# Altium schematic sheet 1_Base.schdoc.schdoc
size 309 x 223 mm; Symbol: Sheet-Symbol_A4; Device: Sheet-Symbol_A4; Company: Velizy Astro Club; Drawed: Paul V.; Reviewed: Denis G.; Version: V1.0; Page Size: A4; @Project Name: AstrOnStep; @Page Count: 2; @Update Date: 2024-04-21; @Create Date: 2024-03-13; @Schematic Name: AstrOnStep SCH; Part Number: AstrOnStep-v1.0; @Page No: 1; @Page Name: Base
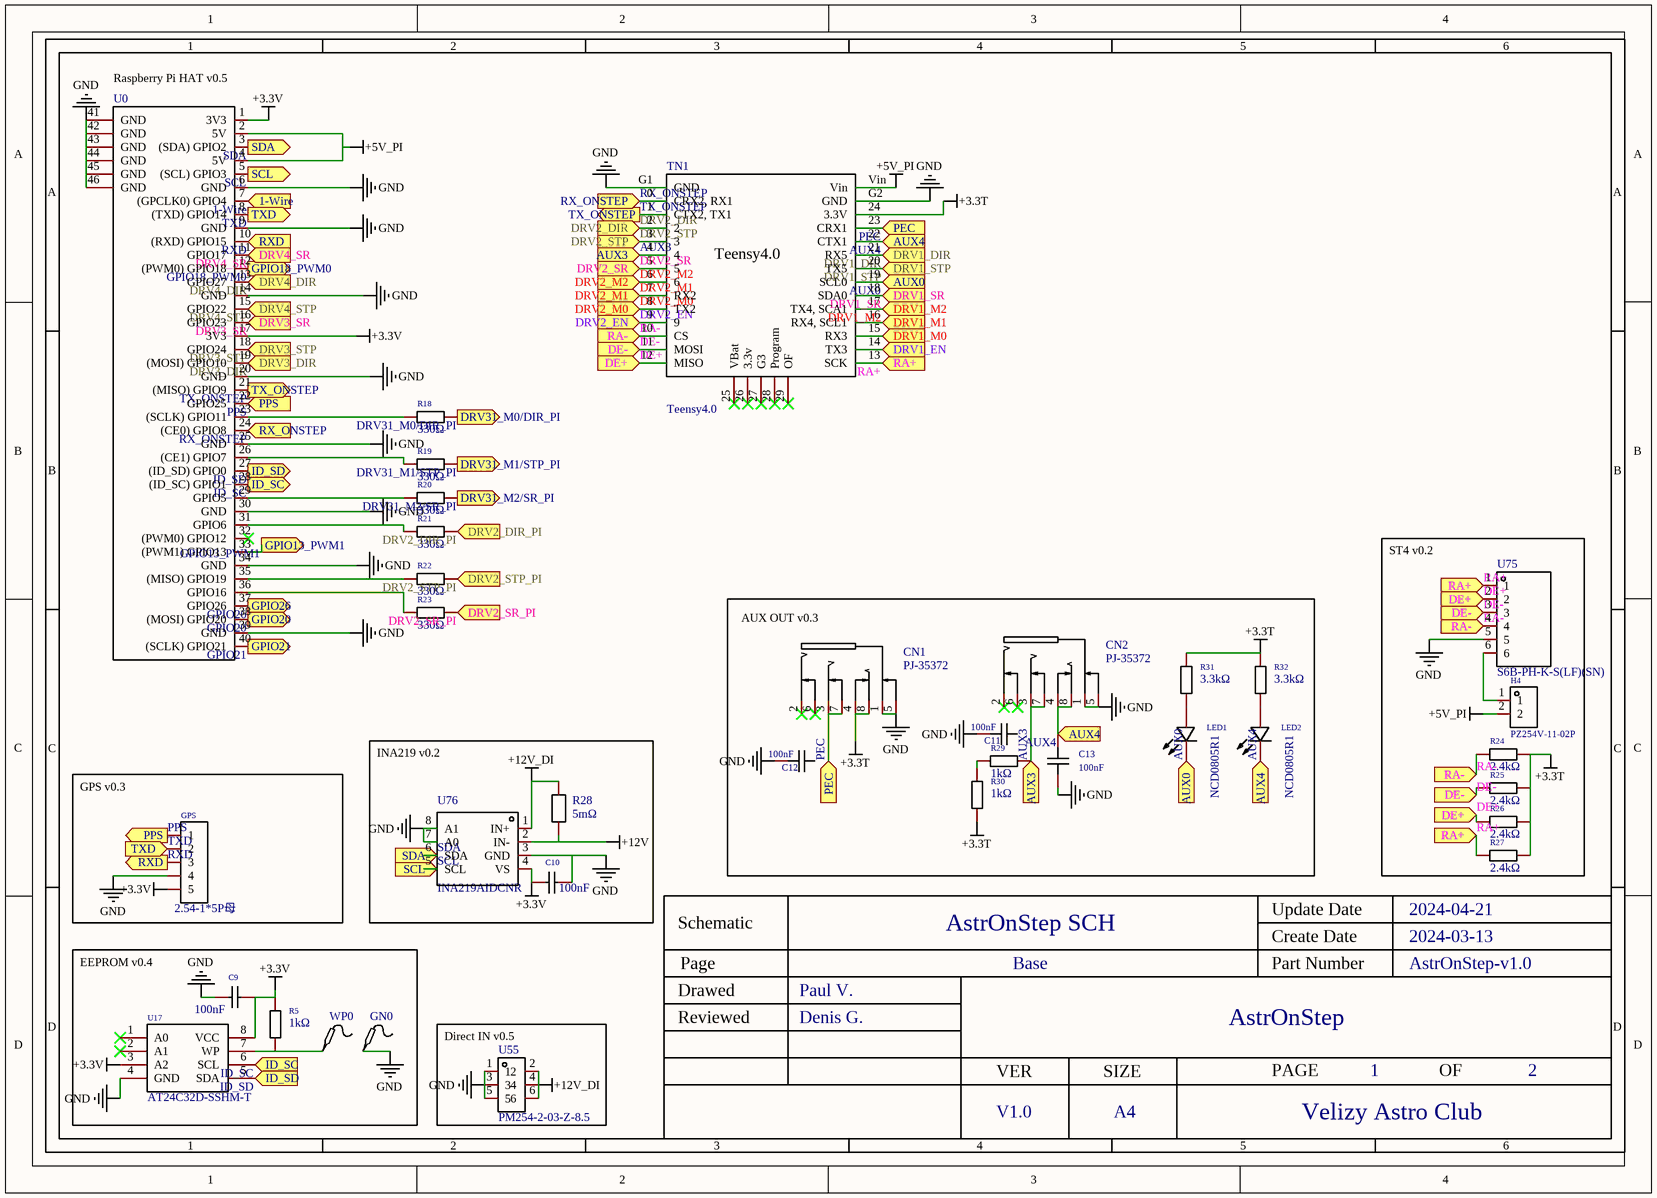
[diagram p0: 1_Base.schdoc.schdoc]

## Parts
C9  100nF  [C0402]
C10  100nF  [C0402]
C11  100nF  [C0603]
C12  100nF  [C0603]
C13  100nF  [C0603]
CN1  PJ-35372  [AUDIO-TH_PJ-35372]
CN2  PJ-35372  [AUDIO-TH_PJ-35372]
GN0  Test-Point  [Test-Point-0.5mm]  (value not drawn)
GPS  2.54-1*5P母  [HDR-TH_5P-P2.54-V-F]
H4  PZ254V-11-02P  [HDR-TH_2P-P2.54-V-M]
LED1  NCD0805R1  [LED0805-R-RD]
LED2  NCD0805R1  [LED0805-R-RD]
R5  1kΩ  [R0402]
R18  330Ω  [R0402]
R19  330Ω  [R0402]
R20  330Ω  [R0402]
R21  330Ω  [R0402]
R22  330Ω  [R0402]
R23  330Ω  [R0402]
R24  2.4kΩ  [R0603]
R25  2.4kΩ  [R0603]
R26  2.4kΩ  [R0603]
R27  2.4kΩ  [R0603]
R28  5mΩ  [R2512]
R29  1kΩ  [R0402]
R30  1kΩ  [R0402]
R31  3.3kΩ  [R0402]
R32  3.3kΩ  [R0402]
TN1  Teensy4.0  [TEENSY4.0]
U0  RASPI HAT FULL  [RASBERRYPI-3-HAT-EXT]  (value not drawn)
U17  AT24C32D-SSHM-T  [SOIC-8_L5.0-W4.0-P1.27-LS6.0-BL]
U55  PM254-2-03-Z-8.5  [HDR-TH_6P-P2.54-V-F-R2-C3-S2.54]
U75  S6B-PH-K-S(LF)(SN)  [CONN-TH_6P-P2.00_S6B-PH-K-S-LF-SN]
U76  INA219AIDCNR  [SOT-23-8_L3.0-W1.7-P0.65-LS2.8-BR]
WP0  Test-Point  [Test-Point-0.5mm]  (value not drawn)

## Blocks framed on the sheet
ST4 v0.2: H4 R24-R27 U75
AUX OUT v0.3: C11-C13 CN1 CN2 LED1 LED2 R29-R32
GPS v0.3: GPS
INA219 v0.2: C10 R28 U76
EEPROM v0.4: C9 GN0 R5 U17 WP0
Direct IN v0.5: U55

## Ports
1-Wire (in), AUX0 (in), AUX3 (in), AUX4 (in), DE+ (in), DE- (in), DRV1_DIR (in), DRV1_EN (in), DRV1_M0 (in), DRV1_M1 (in), DRV1_M2 (in), DRV1_SR (in), DRV1_STP (in), DRV2_DIR (in), DRV2_DIR_PI (in), DRV2_EN (in), DRV2_M0 (in), DRV2_M1 (in), DRV2_M2 (in), DRV2_SR (in), DRV2_SR_PI (in), DRV2_STP (in), DRV2_STP_PI (in), DRV3_DIR (in), DRV3_SR (in), DRV3_STP (in), DRV4_DIR (in), DRV4_SR (in), DRV4_STP (in), DRV31_M0/DIR_PI (out), DRV31_M1/STP_PI (out), DRV31_M2/SR_PI (out), GPIO13_PWM1 (out), GPIO18_PWM0 (out), GPIO20 (out), GPIO21 (out), GPIO26 (out), ID_SC (in), ID_SC (out), ID_SD (in), ID_SD (out), PEC (in), PPS (in), PPS (out), RA+ (in), RA- (in), RX_ONSTEP (in), RXD (in), RXD (out), SCL (in), SCL (out), SDA (in), SDA (out), TX_ONSTEP (out), TXD (in), TXD (out)

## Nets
+3.3T: CN1.4 CN1.8 R24.1 R25.1 R26.1 R27.1 R30.1 R31.2 R32.2 TN1.24(3.3V)
+3.3V: C9.2 C10.1 GPS.5 R5.2 U0.1(3V3) U0.17(3V3) U17.3(A2) U17.8(VCC) U76.4(VS)
+5V_PI: H4.2 TN1.Vin U0.2(5V) U0.4(5V)
+12V: R28.1 U76.2(IN-)
+12V_DI: R28.2 U55.2 U55.4 U55.6 U76.1(IN+)
GND: C9.1 C10.2 C11.2 C12.2 C13.1 CN1.1 CN1.5 CN2.1 CN2.5 GN0.1 GPS.4 TN1.G1(GND) TN1.G2(GND) U0.6(GND) U0.9(GND) U0.14(GND) U0.20(GND) U0.25(GND) U0.30(GND) U0.34(GND) U0.39(GND) U0.41(GND) U0.42(GND) U0.43(GND) U0.44(GND) U0.45(GND) U0.46(GND) U17.4(GND) U55.1 U55.3 U55.5 U75.5 U76.3(GND) U76.7(A0) U76.8(A1)
1-Wire: U0.7((GPCLK0)_GPIO4) ; port 1-Wire
AUX0: LED1.2(-) TN1.19(SCL0) ; port AUX0
AUX3: CN2.3 CN2.7 R29.1 TN1.4 ; port AUX3
AUX4: C13.2 CN2.4 CN2.8 LED2.2(-) TN1.22(CTX1) ; port AUX4
DE+: R26.2 TN1.12(MISO) U75.2 ; port DE+
DE-: R25.2 TN1.11(MOSI) U75.3 ; port DE-
DRV1_DIR: TN1.21(RX5) ; port DRV1_DIR
DRV1_EN: TN1.14(TX3) ; port DRV1_EN
DRV1_M0: TN1.15(RX3) ; port DRV1_M0
DRV1_M1: TN1.16(RX4,_SCL1) ; port DRV1_M1
DRV1_M2: TN1.17(TX4,_SCA1) ; port DRV1_M2
DRV1_SR: TN1.18(SDA0) ; port DRV1_SR
DRV1_STP: TN1.20(TX5) ; port DRV1_STP
DRV2_DIR: TN1.2 ; port DRV2_DIR
DRV2_DIR_PI: R21.2 ; port DRV2_DIR_PI
DRV2_EN: TN1.9 ; port DRV2_EN
DRV2_M0: TN1.8(TX2) ; port DRV2_M0
DRV2_M1: TN1.7(RX2) ; port DRV2_M1
DRV2_M2: TN1.6 ; port DRV2_M2
DRV2_SR: TN1.5 ; port DRV2_SR
DRV2_SR_PI: R23.2 ; port DRV2_SR_PI
DRV2_STP: TN1.3 ; port DRV2_STP
DRV2_STP_PI: R22.2 ; port DRV2_STP_PI
DRV3_DIR: U0.19((MOSI)_GPIO10) ; port DRV3_DIR
DRV3_SR: U0.16(GPIO23) ; port DRV3_SR
DRV3_STP: U0.18(GPIO24) ; port DRV3_STP
DRV4_DIR: U0.13(GPIO27) ; port DRV4_DIR
DRV4_SR: U0.11(GPIO17) ; port DRV4_SR
DRV4_STP: U0.15(GPIO22) ; port DRV4_STP
DRV31_M0/DIR_PI: R18.2 ; port DRV31_M0/DIR_PI
DRV31_M1/STP_PI: R19.2 ; port DRV31_M1/STP_PI
DRV31_M2/SR_PI: R20.2 ; port DRV31_M2/SR_PI
GPIO13_PWM1: U0.33((PWM1)_GPIO13) ; port GPIO13_PWM1
GPIO18_PWM0: U0.12((PWM0)_GPIO18) ; port GPIO18_PWM0
GPIO20: U0.38((MOSI)_GPIO20) ; port GPIO20
GPIO21: U0.40((SCLK)_GPIO21) ; port GPIO21
GPIO26: U0.37(GPIO26) ; port GPIO26
ID_SC: U0.28((ID_SC)_GPIO1) U17.6(SCL) ; port ID_SC
ID_SD: U0.27((ID_SD)_GPIO0) U17.5(SDA) ; port ID_SD
PEC: CN1.3 CN1.7 TN1.23(CRX1) ; port PEC
PPS: GPS.1 U0.22(GPIO25) ; port PPS
RA+: R27.2 TN1.13(SCK) U75.1 ; port RA+
RA-: R24.2 TN1.10(CS) U75.4 ; port RA-
RX_ONSTEP: TN1.0(CRX2,_RX1) U0.24((CE0)_GPIO8) ; port RX_ONSTEP
RXD: GPS.3 U0.10((RXD)_GPIO15) ; port RXD
SCL: U0.5((SCL)_GPIO3) U76.5(SCL) ; port SCL
SDA: U0.3((SDA)_GPIO2) U76.6(SDA) ; port SDA
TX_ONSTEP: TN1.1(CTX2,_TX1) U0.21((MISO)_GPIO9) ; port TX_ONSTEP
TXD: GPS.2 U0.8((TXD)_GPIO14) ; port TXD
NetH4_1: H4.1 U75.6
NetLED1_1: LED1.1(+) R31.1
NetLED2_1: LED2.1(+) R32.1
NetR5_1: R5.1 U17.7(WP) WP0.1
NetR18_1: R18.1 U0.23((SCLK)_GPIO11)
NetR19_1: R19.1 U0.26((CE1)_GPIO7)
NetR20_1: R20.1 U0.29(GPIO5)
NetR21_1: R21.1 U0.31(GPIO6)
NetR22_1: R22.1 U0.35((MISO)_GPIO19)
NetR23_1: R23.1 U0.36(GPIO16)
NetR29_2: R29.2 R30.2

Not connected (* = marked no-connect by the designer): C11 1; C12 1; CN1 2* 6*; CN2 2* 6*; TN1 25(VBat)* 26(3.3v)* 27(G3)* 28(Program)* 29(OF)*; U0 32((PWM0)_GPIO12)*; U17 1(A0)* 2(A1)*

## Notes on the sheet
- (near U0) Raspberry Pi HAT v0.5

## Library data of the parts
C9 C10 = CL05B104KO5NNNC: Manufacturer: SAMSUNG(三星); Add into BOM: yes; Tolerance: ±10%; Description: Capacitance: Tolerance:±10% Tolerance:±10% Voltage Rated: Temperature Coefficient:
C11-C13 = CC0603KRX7R9BB104: Manufacturer: YAGEO(国巨); Add into BOM: yes; Tolerance: ±10%; Description: Capacitance:Tolerance:±10%Tolerance:±10%VoltageRated:TemperatureCoefficient:
CN1 CN2 = PJ-35372: Manufacturer: XKB Connectivity(中国星坤); Add into BOM: yes; Connector Type: 3.5mm耳机座; Current Rating (Max): 0.5A; Voltage Rating (Max): 30V; Welding Temperature (Max): 235℃; Description: Connector Type:3.5mm耳机座 Current Rating (Max):0.5A Voltage Rating (Max):30V Operating Temperature Range:-20℃~+70℃ Operating Temperature Range:-20℃~+70℃ Welding Temperature (Max):235℃
GN0 WP0 = Test-Point: Add into BOM: yes; Description: Test Point 测试点
GPS = 2.54-1*5P母: Manufacturer: BOOMELE(博穆精密); Symbol: Header-Female-2.54_1x5; Add into BOM: no; Convert to PCB: yes; Number of Holes: 5P; Pitch: 2.54mm; Holes Structure: 1x5P; Description: Number of Rows:Plugin Number of Holes:5P Pitch:2.54mm Holes Structure:1x5P Row Spacing:- Mounting Type:Straight Insulation Height:- Contact Material:- Contact Plating:-
H4 = PZ254V-11-02P: Manufacturer: XFCN(兴飞); Add into BOM: no; Convert to PCB: yes; Pitch: 2.54mm; Pin Structure: 1x2P; Circluar Pins/Square Pins: Square Pins; Description: Number of Rows:Plugin Number of Pins:2P Pitch:2.54mm Pin Structure:1x2P Row Spacing:- Mounting Type:Straight Circluar Pins/Square Pins:Square Pins Current Rating (Max):- Voltage Rating (Max):- Length of Mating Pin:6mm Insulation Height:2.5mm Length of End
LED1 LED2 = NCD0805R1_C84256: Manufacturer: 国星光电; Symbol: FC-2012HRK-620D; Add into BOM: yes; Emitted Color: Red; Forward Voltage (VF): 1.6V~2.6V; Forward Current: 20mA; Power Dissipation: 65mW; Lens Color: 无色透明; Dominant Wavelength: 615nm~630nm; Luminous Intensity: 67mcd~195mcd; Viewing Angle: 130°; Description: Emitted Color:Red Diode Configuration:- Lamp Holder Type:- Forward Voltage (VF):1.6V~2.6V Forward Voltage (VF):1.6V~2.6V Forward Current:20mA Power Dissipation:65mW Lens Color:无色透明 Dominant Wavelength:615nm~630nm Dominant Wavelength:615nm~630nm Peak Wavel
R5 R29 R30 = 0402WGF1001TCE: Manufacturer: UNI-ROYAL(厚声); Add into BOM: yes; Tolerance: ±1%; Temperature Coefficient: ±100ppm/℃; Description: Resistance:1000Ω Tolerance:±1% Tolerance:±1% Power(Watts): Overload Voltage (Max): Temperature Coefficient:±100ppm/℃ Temperature Coefficient:±100ppm/℃ Type:Thick Film Resistors Operating Temperature Range:-55℃~+155℃ Operating Temperature Range:-55℃~+155℃
R18-R23 = 0402WGF3300TCE: Manufacturer: UNI-ROYAL(厚声); Add into BOM: yes; Tolerance: ±1%; Temperature Coefficient: ±100ppm/℃; Description: Type:Thick Film Resistors Resistance: Tolerance:±1% Tolerance:±1% Power(Watts): Overload Voltage (Max): Temperature Coefficient:±100ppm/℃ Temperature Coefficient:±100ppm/℃ Operating Temperature Range:-55℃~+155℃ Operating Temperature Range:-55℃~+155℃
R24-R27 = 0603WAF2401T5E: Manufacturer: UNI-ROYAL(厚声); Add into BOM: yes; Tolerance: ±1%; Temperature Coefficient: ±100ppm/℃; Description: Type:Thick Film Resistors Resistance:2.4kΩ Tolerance:±1% Tolerance:±1% Power(Watts): Overload Voltage (Max): Temperature Coefficient:±100ppm/℃ Temperature Coefficient:±100ppm/℃ Operating Temperature Range:-55℃~+155℃ Operating Temperature Range:-55℃~+155℃
R28 = PA2512FKF7T0R005E: Manufacturer: YAGEO(国巨); Add into BOM: yes; Tolerance: ±1%; Temperature Coefficient: ±100ppm/℃; Description: Type: Resistance: Tolerance:±1% Tolerance:±1% Power(Watts): Temperature Coefficient:±100ppm/℃ Temperature Coefficient:±100ppm/℃ Operating Temperature Range:-55℃~+170℃ Operating Temperature Range:-55℃~+170℃
R31 R32 = 0402WGF3301TCE: Manufacturer: UNI-ROYAL(厚声); Add into BOM: yes; Tolerance: ±1%; Temperature Coefficient: ±100ppm/℃; Description: Type:Thick Film Resistors Resistance:3.3kΩ Tolerance:±1% Tolerance:±1% Power(Watts): Overload Voltage (Max): Temperature Coefficient:±100ppm/℃ Temperature Coefficient:±100ppm/℃ Operating Temperature Range:-55℃~+155℃ Operating Temperature Range:-55℃~+155℃
TN1 = Teensy4.0: Add into BOM: no; Convert to PCB: yes
U0 = RASPI HAT FULL - NO OUTLINE: Manufacturer Part: RaspberryPi 3; Convert to PCB: yes; Add into BOM: no
U17 = AT24C32D-SSHM-T: Manufacturer: MICROCHIP(美国微芯); Add into BOM: yes; Interface Type: I2C; Memory Size: 32Kbit; Supply Voltage: 1.7V~5.5V; Description: Interface Type:I2C Memory Size:32Kbit Supply Voltage:1.7V~5.5V Supply Voltage:1.7V~5.5V Operating Temperature:-40℃~+85℃ Operating Temperature:-40℃~+85℃
U55 = PM254-2-03-Z-8.5: Manufacturer: HCTL(华灿天禄); Add into BOM: no; Convert to PCB: yes; Holes Structure: 2x3P; Pitch: 2.54mm; Circular Hole / Square Hole: Square Holes; Number of Holes: 6P; Current Rating (Max): 3A; Holes Direction: Top; Soldering Temperature(Max): 260℃@5S; Description: Holes Structure:2x3P Pitch:2.54mm Row Spacing:2.54mm Circular Hole / Square Hole:Square Holes Mounting Type:Straight Number of Rows:双排 Number of Holes:6P Current Rating (Max):3A Voltage Rating (Max):- Holes Direction:Top Insulation Height:8.5mm Contact Ma
U75 = S6B-PH-K-S(LF)(SN): Manufacturer: JST; Symbol: S6B-PH-K-S-(LF)(SN); Add into BOM: yes; Pins Structure: 1x6P; Pitch: 2mm; Reference Series: PH; Number of PINs Per Row: 6; Description: Pins Structure:1x6P Pitch:2mm Mounting Style:Right-Angle Reference Series:PH Number of Pins:6P Number of Rows:1 Number of PINs Per Row:6 Row Spacing:- Contact Material:Brass
U76 = INA219AIDCNR: Manufacturer: TI(德州仪器); Add into BOM: yes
